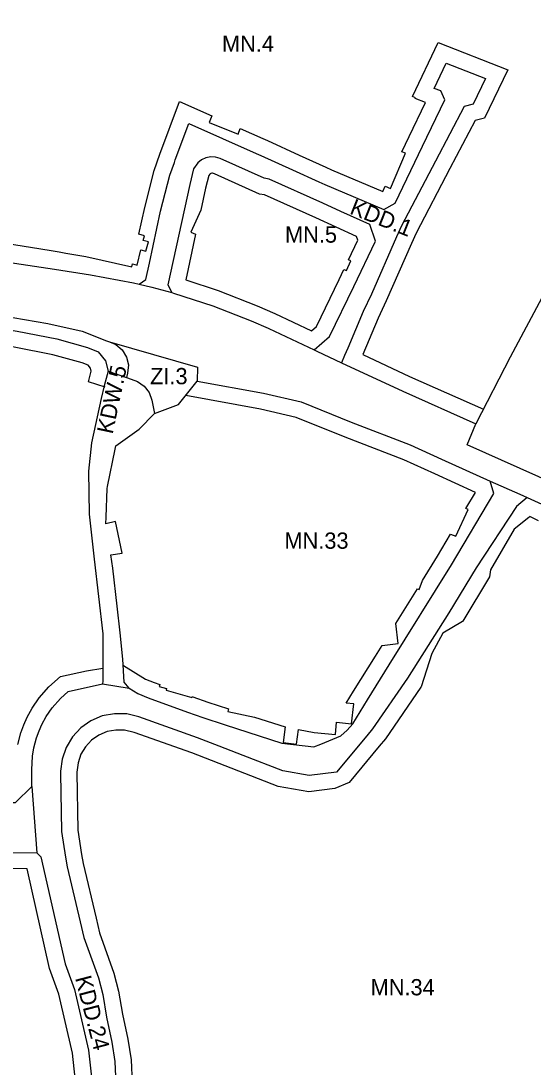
# Model space of a CAD drawing. Extents: x 7414808 to 7417449, y 5544732 to 5546764.
# Drawn here: x 7416075.2 to 7416232.5, y 5545739 to 5546060.4 of the extents above; entities that cross this region are included whole.
import ezdxf

# ---------------------------------------------------------------- set-up
doc = ezdxf.new("R2010")
doc.units = 0
for name, color, linetype in [('LIN_Linie Rozgraniczajace', 7, 'Continuous'), ('LIN_nieprzekraczale linie zabudowy', 7, 'Continuous'), ('TXT_Oznaczenia Przeznaczenia', 7, 'Continuous')]:
    doc.layers.add(name, color=color, linetype=linetype)

msp = doc.modelspace()

# ---------------------------------------------------------------- linework, layer by layer
at = {"layer": 'LIN_Linie Rozgraniczajace'}
msp.add_line((7416078.62, 5545825.18), (7416080.18, 5545804.83), dxfattribs=at)
for points in [[(7416031.71, 5546182.56), (7416063.73, 5546184.03), (7416096.6, 5546180.73), (7416104.92, 5546178.85), (7416103.96, 5546121.51), (7416130.11, 5546113.16), (7416156.81, 5546103.29), (7416174.89, 5546095.8), (7416191.75, 5546088.18), (7416192.64, 5546087.68), (7416211.01, 5546078.61), (7416234.18, 5546068.04), (7416248.86, 5546058.11), (7416257.56, 5546050.25), (7416266.33, 5546042.67), (7416254.64, 5546013.41), (7416236.06, 5545976.82), (7416225.54, 5545957.13), (7416215, 5545936.65)], [(7416111.59, 5545979.53), (7416113.6, 5545980.94), (7416114.7, 5545986.02), (7416118.13, 5546001.92), (7416120.93, 5546013.02), (7416122.38, 5546016.91), (7416122.64, 5546017.78), (7416126.81, 5546028.93), (7416147.53, 5546019.71), (7416148.93, 5546019.09), (7416158.61, 5546014.65), (7416166.79, 5546010.95), (7416168.62, 5546010.11), (7416186.74, 5546002.44), (7416190.2, 5546004.44), (7416198.57, 5546021.9), (7416205.4, 5546036.16), (7416204.25, 5546038.89), (7416202.2, 5546039.67), (7416205.9, 5546047.4), (7416217.93, 5546042.72), (7416214.14, 5546034.81), (7416211.42, 5546034.12), (7416202.6, 5546017.37), (7416192.11, 5545997.43), (7416190.6, 5545994.08), (7416182.92, 5545976.45), (7416180.37, 5545971.11), (7416175.64, 5545959.87), (7416174.65, 5545957.63), (7416173.75, 5545955.37)], [(7416165.32, 5545959.3), (7416170.04, 5545963.49), (7416177.49, 5545978.84), (7416184.14, 5545992.78), (7416182.38, 5545997.83), (7416173.45, 5546001.88), (7416167.93, 5546004.41), (7416151.49, 5546011.83), (7416149.96, 5546012.07), (7416136.48, 5546018.1), (7416135.04, 5546018.55), (7416133.55, 5546018.64), (7416132.07, 5546018.36), (7416130.71, 5546017.74), (7416129.53, 5546016.8), (7416128.28, 5546014.98), (7416127.08, 5546010.16), (7416120.4, 5545979.28), (7416121.63, 5545976.94)], [(7416015.33, 5545995.49), (7416028.49, 5545993.17), (7416037.64, 5545991.43), (7416064.98, 5545987.25), (7416085.59, 5545984.1), (7416096.65, 5545982.41), (7416109.87, 5545979.94), (7416111.59, 5545979.53)], [(7416017.42, 5545981.19), (7416028.93, 5545978.99), (7416058.62, 5545972.09), (7416072.75, 5545969.33), (7416083.51, 5545967.43), (7416094.03, 5545965.04), (7416101.56, 5545962.07), (7416102.47, 5545961.81)], [(7416111.59, 5545979.53), (7416115.5, 5545978.6), (7416121.63, 5545976.94)], [(7416121.63, 5545976.94), (7416122.12, 5545976.8), (7416134.15, 5545972.9), (7416145.91, 5545968.25), (7416151.19, 5545965.96), (7416151.42, 5545965.86), (7416165.32, 5545959.3)], [(7416069.77, 5545965.84), (7416074.06, 5545965.04), (7416086.23, 5545962.71), (7416095.68, 5545960.09), (7416099.01, 5545958.78), (7416101.22, 5545955.99), (7416101.99, 5545952.8)], [(7416102.47, 5545961.81), (7416104.44, 5545960.94), (7416106.36, 5545959.3), (7416107.67, 5545957.14), (7416108.24, 5545954.69), (7416108.02, 5545952.18), (7416107.69, 5545950.84)], [(7416102.47, 5545961.81), (7416129.44, 5545954.05), (7416129.34, 5545949.74)], [(7416165.32, 5545959.3), (7416166.1, 5545958.93), (7416173.75, 5545955.37)], [(7416173.75, 5545955.37), (7416192.52, 5545946.64), (7416215, 5545936.65)], [(7416101.99, 5545952.8), (7416100.86, 5545948.29), (7416099.87, 5545944.41), (7416096.91, 5545930.74), (7416096, 5545922.1), (7416096.18, 5545908.83), (7416097.71, 5545894.99), (7416100.41, 5545872.1), (7416100.43, 5545857.54), (7416100.35, 5545856.67)], [(7416101.99, 5545952.8), (7416107.69, 5545950.84)], [(7416107.69, 5545950.84), (7416110.22, 5545949.97), (7416111.02, 5545949.65), (7416113.11, 5545948.23), (7416114.65, 5545946.23), (7416115.49, 5545943.86), (7416116.24, 5545939.78)], [(7416116.24, 5545939.78), (7416123.69, 5545942.54), (7416129.34, 5545949.74)], [(7416129.34, 5545949.74), (7416149.79, 5545946.05), (7416161.28, 5545943.36), (7416176.65, 5545937.13), (7416194.82, 5545930.2), (7416204.41, 5545925.79), (7416219.37, 5545919.02)], [(7416108.45, 5545855.42), (7416106.93, 5545857.23), (7416106.59, 5545864.27), (7416105.74, 5545872.41), (7416104.81, 5545880.63), (7416103.43, 5545892.29), (7416102.83, 5545896.4), (7416106.34, 5545896.82), (7416104.25, 5545906.56), (7416101.31, 5545905.88), (7416101.39, 5545907.97), (7416101.74, 5545916.72), (7416101.87, 5545917.35), (7416104.19, 5545928.78), (7416104.41, 5545929.83), (7416111.56, 5545934.99), (7416116.24, 5545939.78)], [(7416524.05, 5545784), (7416523.57, 5545784.08), (7416521.98, 5545784.32), (7416516.88, 5545791.94), (7416508.94, 5545787.78), (7416499.67, 5545784.33), (7416490.17, 5545782.33), (7416477.23, 5545781.39), (7416468.1, 5545782.16), (7416464.65, 5545782.87), (7416454.4, 5545785.72), (7416447.92, 5545788.49), (7416436.37, 5545795.2), (7416426.46, 5545803.6), (7416416.42, 5545816.04), (7416406.45, 5545829.85), (7416397.68, 5545840.12), (7416384.46, 5545851.46), (7416374.19, 5545857.96), (7416334.28, 5545876.3), (7416261.17, 5545908.31), (7416212.34, 5545930.15), (7416215, 5545936.65)], [(7416108.45, 5545855.42), (7416111.2, 5545853.73), (7416114.36, 5545852.43), (7416126.37, 5545848.02), (7416131.07, 5545846.38), (7416137.98, 5545844.13), (7416155.43, 5545838.52), (7416165.2, 5545837.33), (7416167.4, 5545838.16), (7416173.51, 5545840.74), (7416175.43, 5545842.47), (7416177.14, 5545844.43), (7416181.66, 5545851.81), (7416188.36, 5545862.52), (7416207.45, 5545893.31), (7416220.53, 5545915.2), (7416219.37, 5545919.02)], [(7416219.37, 5545919.02), (7416222.62, 5545917.55), (7416229.45, 5545914.56), (7416230.76, 5545913.95)], [(7416230.76, 5545913.95), (7416227.49, 5545911.22), (7416215.04, 5545892.33), (7416206.68, 5545878.58), (7416193.93, 5545858.49), (7416183.27, 5545842.94), (7416181.46, 5545840.76), (7416172.2, 5545829.62), (7416163.79, 5545828.56), (7416155.64, 5545829.97), (7416143.5, 5545834.7), (7416136.12, 5545837.58), (7416129.45, 5545840.17), (7416111.44, 5545846.56), (7416107.76, 5545847.45), (7416103.97, 5545847.54), (7416100.24, 5545846.84), (7416096.75, 5545845.37), (7416093.64, 5545843.21), (7416091.05, 5545840.44), (7416089.1, 5545837.19), (7416087.87, 5545833.6), (7416087.42, 5545829.84), (7416087.43, 5545829.27), (7416087.75, 5545811.38), (7416088.91, 5545803.41), (7416089.46, 5545800.51), (7416093.46, 5545783.56), (7416094.55, 5545778.76), (7416099.03, 5545766.33), (7416100.36, 5545761.23), (7416101.55, 5545754.26), (7416103.14, 5545746.64), (7416104.08, 5545740.7), (7416104.41, 5545733.79)], [(7416230.76, 5545913.95), (7416236.34, 5545911.37), (7416239.31, 5545910.01), (7416252.01, 5545904.27), (7416259.34, 5545901.01), (7416272.52, 5545895.39), (7416275.31, 5545894.24), (7416295.55, 5545885.7), (7416301.08, 5545883.36), (7416310.55, 5545879.2), (7416337.49, 5545866.9), (7416343.44, 5545863.96), (7416350.96, 5545860.26), (7416359.11, 5545856.23)], [(7416078.62, 5545825.18), (7416078.63, 5545830.34), (7416078.82, 5545834.5), (7416079.22, 5545837.03), (7416080.04, 5545840.16), (7416080.8, 5545842.29), (7416081.66, 5545844.21), (7416083, 5545846.66), (7416084.84, 5545849.34), (7416087.37, 5545852.23), (7416089.79, 5545854.41), (7416100.35, 5545856.67)], [(7416100.35, 5545856.67), (7416108.45, 5545855.42)], [(7416061.31, 5545820.27), (7416073.62, 5545820.27), (7416078.62, 5545825.18)], [(7415968.5, 5545818.52), (7415979, 5545816.89), (7415981.64, 5545816.49), (7415994.71, 5545812.97), (7416003.69, 5545810.56), (7416013.36, 5545808.66), (7416029.77, 5545805.91), (7416034.85, 5545805.41), (7416055.87, 5545805.01), (7416080.18, 5545804.83), (7416081.41, 5545803.58)], [(7416081.41, 5545803.58), (7416088.85, 5545770.68), (7416091.67, 5545762.78), (7416096.02, 5545744.11), (7416097.23, 5545733.11), (7416097.68, 5545723.46), (7416099.22, 5545718.1), (7416101.6, 5545711.67), (7416105.11, 5545704.09), (7416107.85, 5545699.39), (7416111.82, 5545693.27), (7416115.05, 5545687.84), (7416115.96, 5545686.02)]]:
    msp.add_lwpolyline(points, dxfattribs=at)
at = {"layer": 'LIN_nieprzekraczale linie zabudowy'}
for points in [[(7416059.46, 5545993.83), (7416078.18, 5545990.91), (7416084.55, 5545989.92), (7416086.97, 5545989.42), (7416089.03, 5545989.1), (7416095.18, 5545988.01), (7416109.34, 5545984.89), (7416109.52, 5545985.76), (7416110.92, 5545985.38), (7416112.08, 5545990.1), (7416113.64, 5545989.69), (7416114.39, 5545992.51), (7416112.83, 5545992.92), (7416113.23, 5545994.41), (7416111.49, 5545994.86), (7416113.27, 5546003.06), (7416116.14, 5546014.48), (7416117.95, 5546019.5), (7416123.99, 5546035.66), (7416133.84, 5546031.28), (7416133.01, 5546029.2), (7416141.94, 5546025.66), (7416142.62, 5546027.37), (7416149.56, 5546024.28), (7416150.98, 5546023.65), (7416160.68, 5546019.2), (7416168.86, 5546015.5), (7416170.64, 5546014.68), (7416186.37, 5546008.02), (7416187.14, 5546009.62), (7416188.71, 5546008.91), (7416193.32, 5546019.73), (7416192.21, 5546020.2), (7416194.47, 5546024.91), (7416199.47, 5546035.36), (7416196.31, 5546036.56), (7416196.42, 5546036.83), (7416195.47, 5546037.19), (7416203.4, 5546053.74), (7416224.77, 5546045.42), (7416217.64, 5546030.53), (7416214.8, 5546029.82), (7416207.02, 5546015.04), (7416196.61, 5545995.24), (7416195.17, 5545992.05), (7416187.47, 5545974.37), (7416184.93, 5545969.06), (7416180.22, 5545957.88), (7416194.59, 5545951.19), (7416217.29, 5545941.1)], [(7416164.47, 5545965.23), (7416165.98, 5545966.57), (7416172.98, 5545981.01), (7416174.43, 5545984.04), (7416175.25, 5545983.68), (7416176.55, 5545986.66), (7416175.83, 5545986.97), (7416178.74, 5545993.08), (7416178.36, 5545994.17), (7416165.87, 5545999.86), (7416150.05, 5546007), (7416148.53, 5546007.23), (7416134.71, 5546013.42), (7416134.13, 5546013.6), (7416133.87, 5546013.61), (7416133.59, 5546013.56), (7416133.34, 5546013.45), (7416133.23, 5546013.35), (7416132.91, 5546012.89), (7416131.95, 5546009.03), (7416130.48, 5546002.24), (7416127.41, 5545995.52), (7416128.88, 5545994.85), (7416125.86, 5545980.85), (7416135.85, 5545977.61), (7416147.83, 5545972.87), (7416153.25, 5545970.52), (7416164.47, 5545965.23)], [(7416101.12, 5545947.88), (7416096.01, 5545949.52), (7416096.84, 5545952.82), (7416096.62, 5545953.75), (7416095.93, 5545954.62), (7416094.09, 5545955.34), (7416085.09, 5545957.84), (7416073.13, 5545960.12), (7416068.82, 5545960.93), (7416037.41, 5545967.27), (7416033.27, 5545968), (7416016.53, 5545970.93)], [(7416106.74, 5545862.34), (7416113.47, 5545858.2), (7416116.17, 5545857.09), (7416117.87, 5545856.47), (7416117.71, 5545855.9), (7416119.98, 5545855.26), (7416119.81, 5545854.74), (7416127.77, 5545852.49), (7416127.85, 5545852.8), (7416128.06, 5545852.72), (7416132.68, 5545851.11), (7416138.97, 5545849.07), (7416138.76, 5545848.19), (7416146.98, 5545846.49), (7416156.39, 5545843.46), (7416155.78, 5545838.67), (7416159.88, 5545838.15), (7416160.52, 5545842.65), (7416165.34, 5545841.72), (7416171.82, 5545841.16), (7416172.21, 5545844.91), (7416176.78, 5545844.43), (7416177.5, 5545850.53), (7416175.16, 5545850.77), (7416177.42, 5545854.46), (7416184.13, 5545865.17), (7416186.2, 5545868.51), (7416191.12, 5545869.12), (7416190.38, 5545875.25), (7416197.02, 5545885.93), (7416197.55, 5545885.71), (7416198.57, 5545888.42), (7416203.18, 5545895.92), (7416207.23, 5545902.69), (7416208.78, 5545902.05), (7416212.66, 5545910.25), (7416211.94, 5545910.57), (7416214.91, 5545915.55), (7416202.33, 5545921.24), (7416192.88, 5545925.59), (7416174.82, 5545932.48), (7416159.76, 5545938.58), (7416148.78, 5545941.15), (7416125.85, 5545945.29)], [(7416234.25, 5545906.83), (7416231.53, 5545908.09), (7416231.26, 5545907.86), (7416226.72, 5545904.23), (7416219.49, 5545891.77), (7416219.21, 5545889.57), (7416210.95, 5545875.98), (7416210.9, 5545875.9), (7416204.82, 5545872.27), (7416201.49, 5545866.02), (7416198.15, 5545855.81), (7416198.05, 5545855.67), (7416187.2, 5545839.83), (7416185.3, 5545837.56), (7416176.05, 5545826.42), (7416171.68, 5545824.51), (7416163.67, 5545823.51), (7416154.29, 5545825.13), (7416127.72, 5545835.48), (7416110.02, 5545841.76), (7416107.1, 5545842.46), (7416104.37, 5545842.53), (7416101.69, 5545842.02), (7416099.17, 5545840.97), (7416096.93, 5545839.41), (7416095.07, 5545837.41), (7416093.66, 5545835.07), (7416092.78, 5545832.48), (7416092.43, 5545829.55), (7416092.43, 5545829.32), (7416092.74, 5545811.76), (7416093.84, 5545804.24), (7416094.35, 5545801.55), (7416098.33, 5545784.69), (7416099.36, 5545780.17), (7416103.81, 5545767.81), (7416105.25, 5545762.29), (7416106.46, 5545755.2), (7416108.06, 5545747.54), (7416109.06, 5545741.21), (7416109.4, 5545734.03)], [(7416074.32, 5545838.05), (7416075.26, 5545841.64), (7416076.16, 5545844.16), (7416077.18, 5545846.43), (7416078.73, 5545849.28), (7416080.88, 5545852.41), (7416083.8, 5545855.75), (7416087.44, 5545859.02), (7416095.43, 5545860.73), (7416100.42, 5545861.5)], [(7416092.24, 5545732.72), (7416091.08, 5545743.27), (7416086.87, 5545761.36), (7416084.04, 5545769.29), (7416077.12, 5545799.85), (7416055.8, 5545800.01)]]:
    msp.add_lwpolyline(points, dxfattribs=at)

# ---------------------------------------------------------------- texts
at = {"layer": 'TXT_Oznaczenia Przeznaczenia'}
for s, p in [('MN.4', (7416136.99, 5546050.93)), ('MN.5', (7416156.35, 5545992.28)), ('ZI.3', (7416114.91, 5545948.77)), ('MN.33', (7416156.18, 5545898.22)), ('MN.34', (7416182.64, 5545761))]:
    msp.add_text(s, height=5, dxfattribs=at).set_placement(p)
for s, rotation, p in [('KDD.1', 338.3709, (7416175.93, 5546001.26)), ('KDW.5', 78, (7416103.39, 5545933.25)), ('KDD.24', 284.6336, (7416091.84, 5545766.33))]:
    msp.add_text(s, height=5, rotation=rotation, dxfattribs=at).set_placement(p)

doc.saveas('drawing.dxf')
